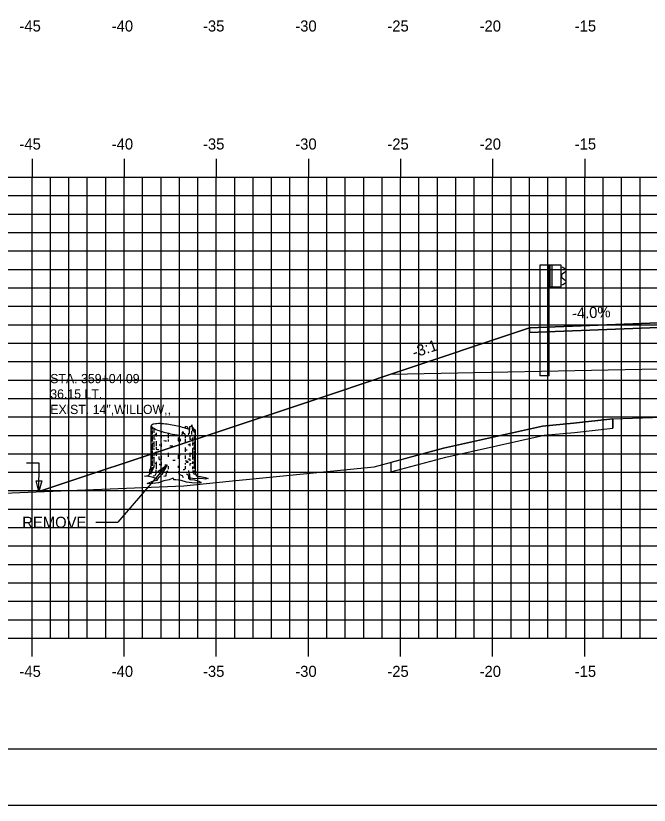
# Model space of a CAD drawing. Extents: x 1146303 to 1146473, y 608981 to 609091.
# Drawn here: x 1146340.03 to 1146374.41, y 608981.28 to 609024.09 of the extents above; entities that cross this region are included whole.
import ezdxf

# ---------------------------------------------------------------- set-up
doc = ezdxf.new("R2010")
doc.units = 0
for name, color, linetype in [('ANNOTATION', 7, 'Continuous'), ('BORDER', 7, 'Continuous'), ('D_Guardrail_Beam_Lt', 7, 'Continuous'), ('D_Roadway_Edge_Shoulder', 7, 'Continuous'), ('D_Roadway_SlopeLines', 7, 'Continuous'), ('D_Roadway_SubGrade', 7, 'Continuous'), ('D_Text_Monospaced', 7, 'Continuous'), ('D_Text_Standard', 7, 'Continuous'), ('H_V ANNOTATION', 7, 'Continuous'), ('MAJOR', 7, 'Continuous'), ('MINOR', 7, 'Continuous'), ('PLOT BOUNDARY', 7, 'Continuous'), ('S_Roadway_Centerline', 7, 'Continuous'), ('S_Trees_Decid_Pay', 7, 'Continuous'), ('SHADING', 7, 'Continuous')]:
    doc.layers.add(name, color=color, linetype=linetype)

msp = doc.modelspace()

# ---------------------------------------------------------------- linework, layer by layer
msp.add_lwpolyline([(1146341.288, 608998.284), (1146357.382, 609003.649), (1146360.382, 609004.649), (1146367.914, 609007.159), (1146367.915, 609007.159), (1146374.915, 609007.439), (1146385.915, 609007.659), (1146396.915, 609007.439), (1146406.316, 609007.063), (1146413.695, 609004.604), (1146416.695, 609003.604), (1146418.924, 609002.861)])
at = {"layer": 'ANNOTATION'}
for p in [(1146348.241, 608999.741), (1146344.376, 608996.62)]:
    msp.add_line(p, (1146345.576, 608996.62), dxfattribs=at)
msp.add_lwpolyline([(1146347.738, 608999.382), (1146348.241, 608999.741), (1146347.966, 608999.187)], close=True, dxfattribs=at)
at = {"layer": 'BORDER'}
msp.add_lwpolyline([(1146310.915, 608984.335), (1146470.915, 608984.335), (1146470.915, 609089.335), (1146310.915, 609089.335)], close=True, dxfattribs=at)
at = {"layer": 'D_Guardrail_Beam_Lt'}
for p, q in [((1146368.485, 609010.558), (1146368.485, 609004.558)), ((1146368.956, 609010.558), (1146368.485, 609010.558)), ((1146369.643, 609010.558), (1146368.956, 609010.558)), ((1146368.956, 609010.558), (1146368.956, 609009.391)), ((1146369.018, 609010.558), (1146369.018, 609009.391)), ((1146369.122, 609010.558), (1146369.122, 609009.391)), ((1146369.643, 609009.391), (1146369.643, 609010.558)), ((1146369.643, 609010.474), (1146369.717, 609010.46)), ((1146369.733, 609010.453), (1146369.877, 609010.353)), ((1146369.648, 609010.009), (1146369.648, 609009.939)), ((1146369.877, 609010.21), (1146369.681, 609010.074)), ((1146369.681, 609009.875), (1146369.877, 609009.739)), ((1146369.717, 609009.489), (1146369.643, 609009.474)), ((1146369.877, 609009.596), (1146369.733, 609009.496)), ((1146368.956, 609009.391), (1146369.643, 609009.391)), ((1146368.976, 609004.558), (1146368.976, 609009.391)), ((1146368.976, 609004.558), (1146368.485, 609004.558))]:
    msp.add_line(p, q, dxfattribs=at)
for centre, major_axis, start_param, end_param in [((1146369.709, 609010.419), (0.0417, 0), 0.959931, 1.376053), ((1146369.826, 609010.282), (0.0877, 0), 5.323254, 7.243116), ((1146369.726, 609010.009), (-0.0789, 0), 5.323254, 6.283185), ((1146369.726, 609009.939), (-0.0789, 0), 6.283185, 7.243116), ((1146369.709, 609009.53), (0.0417, 0), 4.907132, 5.323254), ((1146369.826, 609009.667), (0.0877, 0), 5.323254, 7.243116)]:
    msp.add_ellipse(centre, major_axis=major_axis, ratio=0.995501, start_param=start_param, end_param=end_param, dxfattribs=at)
at = {"layer": 'D_Roadway_Edge_Shoulder'}
msp.add_lwpolyline([(1146374.915, 609007.439), (1146367.915, 609007.159), (1146367.915, 609006.909), (1146374.915, 609007.189)], close=True, dxfattribs=at)
at = {"layer": 'D_Roadway_SlopeLines'}
for points in [[(1146360.382, 609004.649), (1146357.382, 609003.649)], [(1146357.382, 609003.649), (1146341.288, 608998.284)]]:
    msp.add_lwpolyline(points, dxfattribs=at)
at = {"layer": 'D_Roadway_SubGrade'}
for p, q in [((1146372.447, 609002.232), (1146372.447, 609001.732)), ((1146360.382, 608999.869), (1146360.382, 608999.353))]:
    msp.add_line(p, q, dxfattribs=at)
msp.add_lwpolyline([(1146374.915, 609007.023), (1146374.915, 609007.189), (1146367.915, 609006.909), (1146367.915, 609007.159), (1146367.914, 609007.159), (1146360.382, 609004.649), (1146374.915, 609004.939)], close=True, dxfattribs=at)
msp.add_lwpolyline([(1146360.382, 608999.353), (1146363.374, 609000.148), (1146368.706, 609001.337), (1146370.352, 609001.491), (1146372.447, 609001.73)], dxfattribs=at)
at = {"layer": 'D_Text_Standard'}
msp.add_lwpolyline([(1146341.288, 608998.284), (1146341.298, 608999.828), (1146340.618, 608999.828)], dxfattribs=at)
msp.add_lwpolyline([(1146341.288, 608998.284), (1146341.146, 608998.867), (1146341.437, 608998.865)], close=True, dxfattribs=at)
at = {"layer": 'MAJOR'}
for p, q in [((1146340.915, 609016.337), (1146340.915, 609015.335)), ((1146345.915, 609016.337), (1146345.915, 609015.335)), ((1146350.915, 609016.337), (1146350.915, 609015.335)), ((1146355.915, 609016.337), (1146355.915, 609015.335)), ((1146360.915, 609016.337), (1146360.915, 609015.335)), ((1146365.915, 609016.337), (1146365.915, 609015.335)), ((1146370.915, 609016.337), (1146370.915, 609015.335)), ((1146315.915, 609015.335), (1146455.915, 609015.335)), ((1146315.915, 609015.335), (1146455.915, 609015.335)), ((1146340.915, 608990.335), (1146340.915, 609015.335)), ((1146345.915, 608990.335), (1146345.915, 609015.335)), ((1146350.915, 608990.335), (1146350.915, 609015.335)), ((1146355.915, 608990.335), (1146355.915, 609015.335)), ((1146360.915, 608990.335), (1146360.915, 609015.335)), ((1146365.915, 608990.335), (1146365.915, 609015.335)), ((1146370.915, 608990.335), (1146370.915, 609015.335)), ((1146315.915, 609010.335), (1146455.915, 609010.335)), ((1146315.915, 609005.335), (1146455.915, 609005.335)), ((1146315.915, 609000.335), (1146455.915, 609000.335)), ((1146315.915, 608995.335), (1146455.915, 608995.335)), ((1146315.915, 608990.335), (1146455.915, 608990.335)), ((1146315.915, 608990.335), (1146455.915, 608990.335)), ((1146340.915, 608989.333), (1146340.915, 608990.335)), ((1146345.915, 608989.333), (1146345.915, 608990.335)), ((1146350.915, 608989.333), (1146350.915, 608990.335)), ((1146355.915, 608989.333), (1146355.915, 608990.335)), ((1146360.915, 608989.333), (1146360.915, 608990.335)), ((1146365.915, 608989.333), (1146365.915, 608990.335)), ((1146370.915, 608989.333), (1146370.915, 608990.335))]:
    msp.add_line(p, q, dxfattribs=at)
at = {"layer": 'MINOR'}
for p, q in [((1146341.915, 608990.335), (1146341.915, 609015.335)), ((1146342.915, 608990.335), (1146342.915, 609015.335)), ((1146343.915, 608990.335), (1146343.915, 609015.335)), ((1146344.915, 608990.335), (1146344.915, 609015.335)), ((1146346.915, 608990.335), (1146346.915, 609015.335)), ((1146347.915, 608990.335), (1146347.915, 609015.335)), ((1146348.915, 608990.335), (1146348.915, 609015.335)), ((1146349.915, 608990.335), (1146349.915, 609015.335)), ((1146351.915, 608990.335), (1146351.915, 609015.335)), ((1146352.915, 608990.335), (1146352.915, 609015.335)), ((1146353.915, 608990.335), (1146353.915, 609015.335)), ((1146354.915, 608990.335), (1146354.915, 609015.335)), ((1146356.915, 608990.335), (1146356.915, 609015.335)), ((1146357.915, 608990.335), (1146357.915, 609015.335)), ((1146358.915, 608990.335), (1146358.915, 609015.335)), ((1146359.915, 608990.335), (1146359.915, 609015.335)), ((1146361.915, 608990.335), (1146361.915, 609015.335)), ((1146362.915, 608990.335), (1146362.915, 609015.335)), ((1146363.915, 608990.335), (1146363.915, 609015.335)), ((1146364.915, 608990.335), (1146364.915, 609015.335)), ((1146366.915, 608990.335), (1146366.915, 609015.335)), ((1146367.915, 608990.335), (1146367.915, 609015.335)), ((1146368.915, 608990.335), (1146368.915, 609015.335)), ((1146369.915, 608990.335), (1146369.915, 609015.335)), ((1146371.915, 608990.335), (1146371.915, 609015.335)), ((1146372.915, 608990.335), (1146372.915, 609015.335)), ((1146373.915, 608990.335), (1146373.915, 609015.335)), ((1146315.915, 609014.335), (1146455.915, 609014.335)), ((1146315.915, 609013.335), (1146455.915, 609013.335)), ((1146315.915, 609012.335), (1146455.915, 609012.335)), ((1146315.915, 609011.335), (1146455.915, 609011.335)), ((1146315.915, 609009.335), (1146455.915, 609009.335)), ((1146315.915, 609008.335), (1146455.915, 609008.335)), ((1146315.915, 609007.335), (1146455.915, 609007.335)), ((1146315.915, 609006.335), (1146455.915, 609006.335)), ((1146315.915, 609004.335), (1146455.915, 609004.335)), ((1146315.915, 609003.335), (1146455.915, 609003.335)), ((1146315.915, 609002.335), (1146455.915, 609002.335)), ((1146315.915, 609001.335), (1146455.915, 609001.335)), ((1146315.915, 608999.335), (1146455.915, 608999.335)), ((1146315.915, 608998.335), (1146455.915, 608998.335)), ((1146315.915, 608997.335), (1146455.915, 608997.335)), ((1146315.915, 608996.335), (1146455.915, 608996.335)), ((1146315.915, 608994.335), (1146455.915, 608994.335)), ((1146315.915, 608993.335), (1146455.915, 608993.335)), ((1146315.915, 608992.335), (1146455.915, 608992.335)), ((1146315.915, 608991.335), (1146455.915, 608991.335))]:
    msp.add_line(p, q, dxfattribs=at)
at = {"layer": 'PLOT BOUNDARY'}
msp.add_lwpolyline([(1146302.822, 608981.276), (1146472.822, 608981.276), (1146472.822, 609091.276), (1146302.822, 609091.276)], close=True, dxfattribs=at)
at = {"layer": 'S_Roadway_Centerline'}
msp.add_lwpolyline([(1146333.102, 608997.996), (1146337.13, 608998.116), (1146349.153, 608998.601), (1146351.613, 608998.852), (1146359.482, 608999.63), (1146363.256, 609000.633), (1146368.628, 609001.831), (1146370.301, 609001.988), (1146372.447, 609002.232), (1146378.334, 609002.421), (1146383.797, 609002.585), (1146389.233, 609002.425), (1146394.809, 609002.215), (1146396.683, 609001.977), (1146398.464, 609001.775), (1146403.062, 608998.9), (1146403.617, 608998.566), (1146408.502, 609000.653), (1146410.677, 609001.551), (1146412.036, 609001.76), (1146432.73, 609005.067)], dxfattribs=at)
at = {"layer": 'S_Trees_Decid_Pay'}
for p, q in [((1146347.44, 609001.766), (1146347.44, 609001.645)), ((1146347.44, 609001.593), (1146347.44, 609001.379)), ((1146347.44, 609001.334), (1146347.44, 609000.996)), ((1146347.52, 609001.721), (1146347.52, 609001.468)), ((1146347.52, 609001.371), (1146347.52, 609001.107)), ((1146347.652, 609001.468), (1146347.652, 609001.276)), ((1146347.925, 609001.554), (1146347.925, 609001.468)), ((1146347.925, 609001.327), (1146347.925, 609001.188)), ((1146348.308, 609001.453), (1146348.308, 609001.173)), ((1146349.219, 609001.315), (1146349.219, 609001.196)), ((1146349.48, 609001.314), (1146349.48, 609001.109)), ((1146349.564, 609001.562), (1146349.564, 609001.388)), ((1146349.714, 609001.362), (1146349.714, 609001.107)), ((1146347.44, 609000.879), (1146347.44, 609000.518)), ((1146347.52, 609001.01), (1146347.52, 609000.702)), ((1146347.652, 609001.025), (1146347.652, 609000.747)), ((1146347.925, 609000.901), (1146347.925, 609000.71)), ((1146348.308, 609001.107), (1146348.308, 609001.004)), ((1146348.854, 609001.216), (1146348.854, 609001.037)), ((1146348.98, 609001.044), (1146348.975, 609001.151)), ((1146349.219, 609001.144), (1146349.219, 609000.959)), ((1146349.48, 609000.901), (1146349.48, 609000.747)), ((1146349.628, 609001.216), (1146349.628, 609001.004)), ((1146349.628, 609000.939), (1146349.628, 609000.791)), ((1146349.714, 609001.01), (1146349.714, 609000.541)), ((1146347.44, 609000.482), (1146347.44, 609000.033)), ((1146347.52, 609000.613), (1146347.52, 609000.547)), ((1146347.652, 609000.702), (1146347.652, 609000.593)), ((1146347.652, 609000.459), (1146347.652, 609000.23)), ((1146349.219, 609000.673), (1146349.219, 609000.445)), ((1146349.628, 609000.613), (1146349.628, 609000.313)), ((1146349.714, 609000.49), (1146349.714, 609000.356)), ((1146347.52, 609000.313), (1146347.52, 609000.216)), ((1146347.52, 609000.165), (1146347.52, 608999.804)), ((1146347.925, 609000.23), (1146347.925, 609000.022)), ((1146348.308, 609000.393), (1146348.308, 609000.172)), ((1146348.854, 609000.258), (1146348.854, 609000.062)), ((1146349.219, 609000.247), (1146349.219, 609000.062)), ((1146349.48, 609000.384), (1146349.48, 609000.165)), ((1146349.48, 609000.065), (1146349.48, 608999.944)), ((1146349.628, 609000.275), (1146349.628, 609000.033)), ((1146349.714, 609000.298), (1146349.714, 608999.973)), ((1146347.44, 608999.967), (1146347.44, 608999.685)), ((1146347.52, 608999.753), (1146347.52, 608999.586)), ((1146347.652, 608999.901), (1146347.652, 608999.518)), ((1146347.925, 608999.901), (1146347.925, 608999.701)), ((1146348.308, 608999.672), (1146348.308, 608999.499)), ((1146348.854, 608999.678), (1146348.854, 608999.575)), ((1146349.219, 608999.827), (1146349.219, 608999.75)), ((1146349.219, 608999.672), (1146349.219, 608999.499)), ((1146349.48, 608999.793), (1146349.48, 608999.695)), ((1146349.628, 608999.922), (1146349.628, 608999.781)), ((1146349.628, 608999.649), (1146349.628, 608999.493)), ((1146349.714, 608999.944), (1146349.714, 608999.524)), ((1146347.929, 608999.444), (1146347.849, 608999.312)), ((1146349.711, 608999.421), (1146349.725, 608999.304))]:
    msp.add_line(p, q, dxfattribs=at)
for points in [[(1146349.765, 609001.636), (1146349.765, 608999.499), (1146349.785, 608999.357), (1146349.791, 608999.232), (1146349.834, 608999.145), (1146349.927, 608999.096), (1146350.062, 608999.096), (1146350.306, 608999.04), (1146350.473, 608998.991), (1146350.33, 608998.96), (1146350.093, 608998.997), (1146349.883, 608998.985), (1146349.622, 608998.991), (1146349.498, 608999.009), (1146349.468, 608998.966), (1146349.406, 608999.009), (1146349.505, 608998.941), (1146349.74, 608998.917), (1146349.97, 608998.855), (1146350.1, 608998.785), (1146350.001, 608998.741), (1146349.579, 608998.76), (1146349.301, 608998.804), (1146349.002, 608998.88), (1146348.716, 608998.917), (1146348.611, 608998.917), (1146348.593, 608998.997), (1146348.524, 608999.003), (1146348.358, 608998.917), (1146348.072, 608998.861), (1146347.773, 608998.754), (1146347.314, 608998.705), (1146347.16, 608998.717), (1146347.501, 608998.867), (1146347.705, 608998.898), (1146347.693, 608998.972), (1146347.433, 608999.071), (1146347.258, 608999.102), (1146347.017, 608999.114), (1146347.215, 608999.151), (1146347.277, 608999.188), (1146347.301, 608999.275), (1146347.314, 608999.444), (1146347.359, 608999.53), (1146347.387, 608999.771), (1146347.387, 609001.857)], [(1146349.386, 609001.675), (1146349.365, 609001.783), (1146349.233, 609001.814), (1146349.226, 609001.726)], [(1146349.408, 609001.309), (1146349.416, 609001.453), (1146349.461, 609001.445), (1146349.476, 609001.82), (1146349.57, 609001.828), (1146349.585, 609001.908), (1146349.622, 609001.571), (1146349.667, 609001.665), (1146349.688, 609001.511), (1146349.765, 609001.636), (1146349.759, 609001.447)], [(1146349.765, 609001.636), (1146349.719, 609001.659), (1146349.696, 609001.725), (1146349.644, 609001.748), (1146349.611, 609001.673)], [(1146349.247, 609001.314), (1146349.21, 609001.417), (1146349.144, 609001.422), (1146349.144, 609001.504), (1146349.07, 609001.511), (1146349.045, 609001.331)], [(1146347.811, 609000.036), (1146347.812, 609000.113), (1146347.82, 609000.179)], [(1146347.438, 608999.613), (1146347.377, 608999.452), (1146347.364, 608999.327), (1146347.371, 608999.23)], [(1146349.356, 608999.944), (1146349.365, 608999.87), (1146349.291, 608999.864), (1146349.276, 608999.981)], [(1146347.495, 608999.532), (1146347.423, 608999.429), (1146347.423, 608999.304)], [(1146347.635, 608999.458), (1146347.635, 608999.253), (1146347.578, 608999.143), (1146347.48, 608999.127)], [(1146347.705, 608998.898), (1146347.791, 608999.04), (1146347.923, 608999.182)], [(1146348.29, 608999.384), (1146348.187, 608999.333), (1146348.173, 608999.127), (1146348.07, 608999.098)], [(1146348.856, 608999.392), (1146348.873, 608999.238), (1146349.07, 608999.157), (1146349.116, 608999.054)], [(1146349.307, 608999.256), (1146349.381, 608999.188), (1146349.4, 608999.09), (1146349.406, 608999.009)], [(1146349.498, 608999.009), (1146349.48, 608999.188), (1146349.418, 608999.325), (1146349.425, 608999.425)], [(1146349.644, 608999.429), (1146349.651, 608999.304), (1146349.733, 608999.209)]]:
    msp.add_lwpolyline(points, dxfattribs=at)
for centre, radius, start, end in [((1146347.434, 609001.857), 0.0467, 169.2221, 180.9043), ((1146347.442, 609001.857), 0.0544, 180.9043, 191.7221), ((1146347.434, 609001.857), 0.0467, 157.54, 169.2221), ((1146347.451, 609001.859), 0.0645, 191.7221, 204.3989), ((1146347.441, 609001.854), 0.0544, 146.7221, 157.54), ((1146347.49, 609001.877), 0.107, 204.3989, 214.2221), ((1146347.449, 609001.849), 0.0645, 134.0453, 146.7221), ((1146347.537, 609001.909), 0.164, 214.2221, 228.4286), ((1146347.479, 609001.818), 0.107, 124.2221, 134.0453), ((1146347.511, 609001.771), 0.164, 110.0157, 124.2221), ((1146347.747, 609002.145), 0.48, 228.4286, 236.7221), ((1146347.619, 609001.474), 0.48, 101.7221, 110.0157), ((1146348.196, 609002.83), 1.299, 236.7221, 252.1387), ((1146347.786, 609000.672), 1.299, 86.3056, 101.7221), ((1146347.475, 608995.855), 6.126, 79.2221, 86.3056), ((1146347.475, 608995.855), 6.126, 72.1387, 79.2221), ((1146347.441, 609001.53), 0.0554, 191.6815, 202.5), ((1146347.451, 609001.534), 0.0657, 202.5, 215.1737), ((1146347.486, 609001.559), 0.109, 215.1737, 225), ((1146347.527, 609001.6), 0.166, 225, 238.33), ((1146347.999, 609002.619), 1.292, 250.9084, 254.4349), ((1146349.677, 609007.424), 6.126, 252.1387, 259.2221), ((1146348.575, 609007.207), 5.916, 263.6913, 265.0485), ((1146349.677, 609007.424), 6.126, 259.2221, 264.0853), ((1146349.677, 609007.424), 6.126, 265.9754, 266.3056), ((1146349.366, 609002.608), 1.299, 266.3056, 271.8711), ((1146348.955, 609000.449), 1.299, 66.6931, 72.1387), ((1146347.442, 609001.27), 0.0554, 191.6815, 202.5), ((1146347.452, 609001.274), 0.0657, 202.5, 215.1737), ((1146347.487, 609001.299), 0.109, 215.1737, 225), ((1146347.528, 609001.339), 0.166, 225, 239.1924), ((1146347.528, 609001.076), 0.166, 238.3999, 239.1924), ((1146347.691, 609001.612), 0.484, 239.1924, 242.5838), ((1146347.691, 609001.348), 0.484, 239.1924, 247.5), ((1146348, 609002.358), 1.292, 247.5, 251.9171), ((1146348, 609002.095), 1.292, 247.5, 248.1929), ((1146348.576, 609006.946), 5.916, 265.1076, 266.4618), ((1146348.576, 609006.946), 5.916, 272.6957, 273.9224), ((1146349.152, 609002.358), 1.292, 284.7144, 289.3881), ((1146349.152, 609002.095), 1.292, 291.6463, 292.5), ((1146349.461, 609001.348), 0.484, 292.5, 300.8076), ((1146349.623, 609001.339), 0.166, 300.8076, 315), ((1146349.623, 609001.076), 0.166, 300.8076, 302.9622), ((1146349.664, 609001.299), 0.109, 315, 324.8263), ((1146349.7, 609001.274), 0.0657, 324.8263, 337.5), ((1146349.709, 609001.27), 0.0554, 337.5, 348.3185), ((1146349.717, 609001.268), 0.0476, 348.3185, 0), ((1146347.442, 609000.749), 0.0554, 191.6815, 202.5), ((1146347.442, 609000.491), 0.0554, 191.6815, 202.5), ((1146347.452, 609000.753), 0.0657, 202.5, 215.1737), ((1146347.452, 609000.495), 0.0657, 202.5, 215.1737), ((1146347.487, 609000.778), 0.109, 215.1737, 225), ((1146347.487, 609000.52), 0.109, 215.1737, 225), ((1146347.528, 609000.818), 0.166, 225, 239.1924), ((1146347.528, 609000.561), 0.166, 225, 237.9306), ((1146347.691, 609001.091), 0.484, 239.1924, 245.3628), ((1146348, 609001.837), 1.292, 254.3895, 260.7435), ((1146348, 609002.095), 1.292, 261.6338, 262.8454), ((1146348.576, 609006.683), 5.916, 262.8454, 263.6816), ((1146348.576, 609006.683), 5.916, 268.2292, 269.8838), ((1146348.576, 609006.425), 5.916, 276.2405, 277.1546), ((1146349.152, 609001.837), 1.292, 277.1546, 278.1274), ((1146349.152, 609002.095), 1.292, 280.7368, 284.7144), ((1146349.152, 609001.837), 1.292, 291.5158, 292.5), ((1146349.461, 609001.091), 0.484, 294.2275, 300.8076), ((1146349.623, 609000.818), 0.166, 300.8076, 315), ((1146349.623, 609000.561), 0.166, 300.8076, 315), ((1146349.664, 609000.778), 0.109, 315, 324.8263), ((1146349.664, 609000.52), 0.109, 315, 324.8263), ((1146349.7, 609000.753), 0.0657, 324.8263, 337.5), ((1146349.7, 609000.495), 0.0657, 324.8263, 337.5), ((1146349.709, 609000.749), 0.0554, 337.5, 348.3185), ((1146349.709, 609000.491), 0.0554, 337.5, 348.3185), ((1146349.717, 609000.747), 0.0476, 348.3185, 0), ((1146349.717, 609000.49), 0.0476, 348.3185, 0), ((1146347.442, 609000.226), 0.0554, 191.6815, 202.5), ((1146347.528, 609000.295), 0.166, 237.9306, 239.1924), ((1146347.691, 609000.568), 0.484, 239.1924, 247.5), ((1146348, 609001.58), 1.292, 249.8999, 254.3895), ((1146348, 609001.314), 1.292, 261.6205, 262.8454), ((1146348.576, 609005.902), 5.916, 262.8454, 263.6816), ((1146348.576, 609006.168), 5.916, 272.6957, 273.7279), ((1146349.152, 609001.314), 1.292, 280.7537, 284.7144), ((1146349.152, 609001.58), 1.292, 288.201, 292.5), ((1146349.152, 609001.314), 1.292, 291.6463, 292.5), ((1146349.461, 609000.568), 0.484, 292.5, 300.8076), ((1146349.623, 609000.295), 0.166, 300.8076, 315), ((1146349.664, 609000.255), 0.109, 315, 324.8263), ((1146349.7, 609000.23), 0.0657, 324.8263, 337.5), ((1146349.709, 609000.226), 0.0554, 337.5, 348.3185), ((1146349.717, 609000.224), 0.0476, 348.3185, 0), ((1146347.442, 608999.954), 0.0554, 191.6815, 202.5), ((1146347.452, 608999.958), 0.0657, 202.5, 215.1737), ((1146347.487, 608999.983), 0.109, 215.1737, 225), ((1146347.528, 609000.023), 0.166, 225, 237.9306), ((1146347.691, 609000.039), 0.484, 243.4501, 247.5), ((1146347.991, 609000.789), 1.292, 247.9396, 248.6304), ((1146348, 609001.043), 1.292, 250.8466, 254.3895), ((1146348, 609001.043), 1.292, 261.6338, 262.8454), ((1146348.576, 609005.631), 5.916, 262.8454, 263.6816), ((1146348.576, 609005.631), 5.916, 265.539, 266.7363), ((1146348.576, 609005.902), 5.916, 269.7243, 270), ((1146348.576, 609005.902), 5.916, 270, 271.0793), ((1146349.152, 609001.043), 1.292, 284.7144, 288.6336), ((1146349.152, 609000.785), 1.292, 291.6463, 292.5), ((1146349.461, 609000.296), 0.484, 292.5, 297.266), ((1146349.461, 609000.039), 0.484, 292.5, 300.8076), ((1146349.623, 608999.766), 0.166, 300.8076, 315), ((1146349.664, 608999.725), 0.109, 315, 324.8263), ((1146349.7, 608999.7), 0.0657, 324.8263, 337.5), ((1146349.709, 608999.697), 0.0554, 337.5, 348.3185), ((1146349.717, 608999.695), 0.0476, 348.3185, 0), ((1146348.576, 609005.373), 5.916, 275.2344, 276.2169)]:
    msp.add_arc(centre, radius, start, end, dxfattribs=at)
at = {"layer": 'SHADING'}
for p, q in [((1146372.447, 609001.732), (1146372.447, 609002.232)), ((1146360.382, 608999.869), (1146360.382, 608999.353))]:
    msp.add_line(p, q, dxfattribs=at)
for points in [[(1146372.447, 609002.232), (1146370.301, 609001.988), (1146368.628, 609001.831), (1146363.256, 609000.633), (1146360.382, 608999.869)], [(1146360.382, 608999.353), (1146363.374, 609000.148), (1146368.706, 609001.337), (1146370.352, 609001.491), (1146372.447, 609001.732)]]:
    msp.add_lwpolyline(points, dxfattribs=at)

# ---------------------------------------------------------------- texts
at = {"layer": 'ANNOTATION'}
for s, rotation, p in [('-4.0%', 2.2906, (1146370.231, 609007.653)), ('-3:1', 18.4348, (1146361.665, 609005.53))]:
    msp.add_text(s, height=0.6, rotation=rotation, dxfattribs=at).set_placement(p)
msp.add_text('REMOVE', height=0.6, dxfattribs=at).set_placement((1146340.384, 608996.32))
at = {"layer": 'D_Text_Monospaced'}
for s, height, p in [('STA. 359+04.09', 0.49998, (1146341.902, 609004.164)), ('36.15 LT.', 0.5, (1146341.902, 609003.33)), ('EXIST. 14",WILLOW,,', 0.49998, (1146341.902, 609002.49))]:
    msp.add_text(s, height=height, dxfattribs=at).set_placement(p)
at = {"layer": 'H_V ANNOTATION'}
for s, p in [('-45', (1146340.232, 609023.235)), ('-40', (1146345.24, 609023.235)), ('-35', (1146350.195, 609023.235)), ('-30', (1146355.203, 609023.235)), ('-25', (1146360.2, 609023.235)), ('-20', (1146365.208, 609023.235)), ('-15', (1146370.372, 609023.235)), ('-45', (1146340.232, 609016.835)), ('-40', (1146345.24, 609016.835)), ('-35', (1146350.195, 609016.835)), ('-30', (1146355.203, 609016.835)), ('-25', (1146360.2, 609016.835)), ('-20', (1146365.208, 609016.835)), ('-15', (1146370.372, 609016.835)), ('-45', (1146340.232, 608988.235)), ('-40', (1146345.24, 608988.235)), ('-35', (1146350.195, 608988.235)), ('-30', (1146355.203, 608988.235)), ('-25', (1146360.2, 608988.235)), ('-20', (1146365.208, 608988.235)), ('-15', (1146370.372, 608988.235))]:
    msp.add_text(s, height=0.6, dxfattribs=at).set_placement(p)

doc.saveas('drawing.dxf')
